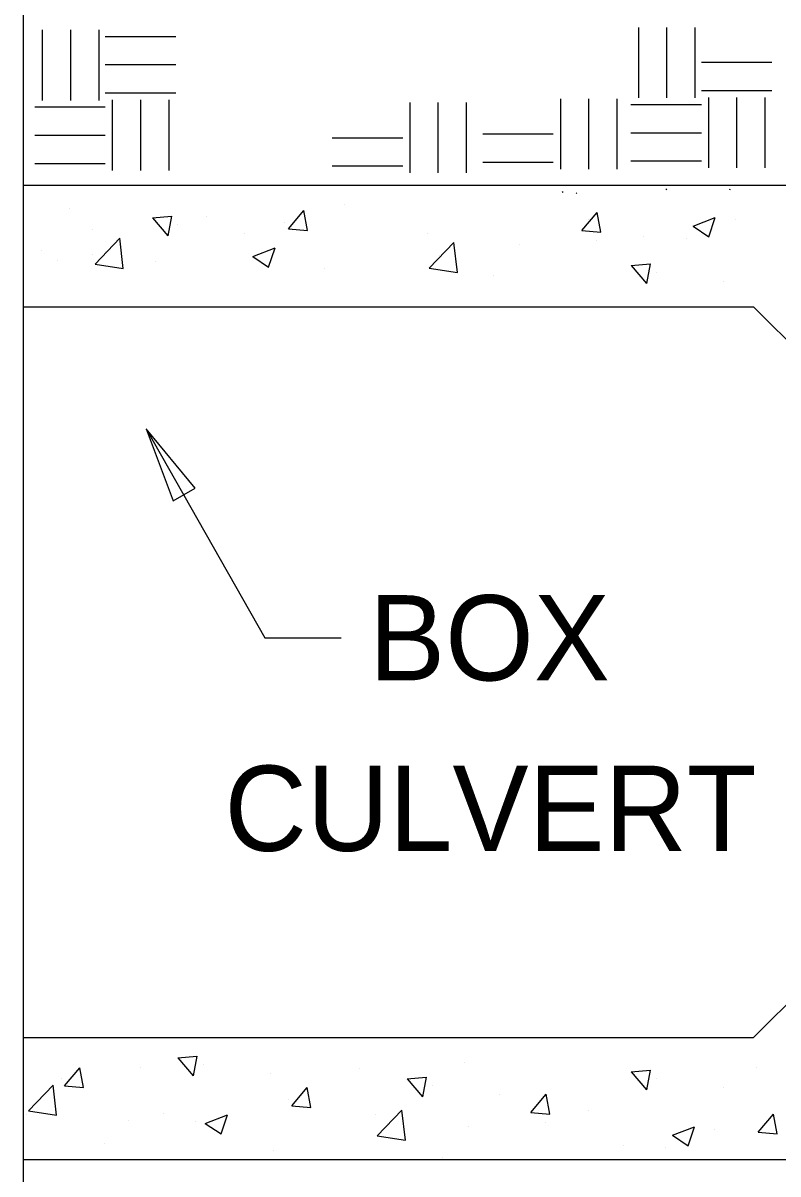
# Model space of a CAD drawing. Extents: x -1609 to 1184, y -412 to 394.
# Drawn here: x 598.388 to 600.868, y 242.766 to 246.546 of the extents above; entities that cross this region are included whole.
import ezdxf

# ---------------------------------------------------------------- set-up
doc = ezdxf.new("R2010")
doc.units = 0
for name, color, linetype in [('Default', 7, 'Continuous'), ('SH_Data', 7, 'Continuous'), ('ST_Text', 7, 'Continuous')]:
    doc.layers.add(name, color=color, linetype=linetype)

msp = doc.modelspace()

# ---------------------------------------------------------------- linework, layer by layer
at = {"layer": 'Default'}
for p, q in [((598.3883, 247.6355), (598.3883, 240.0476)), ((598.3883, 246.0133), (607.4734, 246.0133)), ((598.3883, 246.0133), (601.4383, 246.0133)), ((599.4451, 245.9484), (599.4451, 245.9484)), ((598.5411, 245.9371), (598.5411, 245.9371)), ((598.8141, 245.9061), (598.8764, 245.9116)), ((598.8141, 245.9061), (598.8643, 245.8463)), ((598.8764, 245.9116), (598.8643, 245.8463)), ((598.9918, 245.9118), (598.9918, 245.9118)), ((599.2603, 245.8701), (599.3105, 245.9299)), ((599.3225, 245.8646), (599.3105, 245.9299)), ((600.2242, 245.8638), (600.2744, 245.9236)), ((600.2449, 245.9018), (600.2449, 245.9018)), ((600.2864, 245.8583), (600.2744, 245.9236)), ((600.5895, 245.879), (600.6624, 245.907)), ((600.6413, 245.844), (600.6624, 245.9069)), ((598.6179, 245.8687), (598.6179, 245.8687)), ((598.8969, 245.8839), (598.8969, 245.8839)), ((599.2481, 245.8902), (599.2481, 245.8902)), ((599.2603, 245.8701), (599.3225, 245.8646)), ((600.2242, 245.8638), (600.2864, 245.8583)), ((600.5895, 245.879), (600.6413, 245.844)), ((600.7276, 245.8988), (600.7276, 245.8988)), ((598.6252, 245.7542), (598.7063, 245.8387)), ((598.7178, 245.7398), (598.7063, 245.8387)), ((599.1174, 245.853), (599.1174, 245.853)), ((599.7156, 245.8551), (599.7156, 245.8551)), ((599.7228, 245.7406), (599.8039, 245.8251)), ((599.8155, 245.7262), (599.8039, 245.8251)), ((600.2714, 245.8316), (600.2714, 245.8316)), ((600.4281, 245.8448), (600.4281, 245.8448)), ((600.5673, 245.8381), (600.5673, 245.8381)), ((598.4475, 245.799), (598.4475, 245.799)), ((598.66, 245.796), (598.66, 245.796)), ((599.1435, 245.7793), (599.2164, 245.8073)), ((599.1953, 245.7444), (599.2164, 245.8073)), ((600.0183, 245.8167), (600.0183, 245.8167)), ((598.5007, 245.7651), (598.5007, 245.7651)), ((598.6164, 245.7857), (598.6164, 245.7857)), ((598.6252, 245.7542), (598.7178, 245.7398)), ((598.8233, 245.7622), (598.8233, 245.7622)), ((599.1435, 245.7794), (599.1953, 245.7444)), ((599.7576, 245.7824), (599.7576, 245.7824)), ((600.3858, 245.7498), (600.4481, 245.7552)), ((600.3858, 245.7498), (600.436, 245.69)), ((600.4481, 245.7553), (600.436, 245.69)), ((599.3792, 245.7387), (599.3792, 245.7387)), ((599.7228, 245.7406), (599.8154, 245.7262)), ((599.9351, 245.7152), (599.9351, 245.7152)), ((600.4686, 245.7275), (600.4686, 245.7275)), ((600.6891, 245.6967), (600.6891, 245.6967)), ((598.3883, 245.6133), (600.7883, 245.6133)), ((600.7883, 245.6133), (601.1217, 245.28)), ((601.1217, 243.5467), (600.7883, 243.2133)), ((598.3883, 243.2133), (600.7883, 243.2133)), ((598.8969, 243.1472), (598.9591, 243.1526)), ((598.8969, 243.1472), (598.9471, 243.0874)), ((598.9591, 243.1527), (598.9471, 243.0874)), ((598.5248, 243.0547), (598.575, 243.1145)), ((598.5871, 243.0492), (598.5751, 243.1145)), ((598.774, 243.1148), (598.774, 243.1148)), ((598.9797, 243.1249), (598.9797, 243.1249)), ((599.4943, 243.1117), (599.4943, 243.1117)), ((599.8381, 243.1316), (599.8381, 243.1316)), ((600.3858, 243.1012), (600.4481, 243.1067)), ((600.4481, 243.1067), (600.436, 243.0414)), ((600.7979, 243.115), (600.7979, 243.115)), ((598.5133, 243.0805), (598.5133, 243.0805)), ((599.2001, 243.0941), (599.2001, 243.0941)), ((599.6505, 243.0782), (599.7128, 243.0837)), ((599.6505, 243.0782), (599.7007, 243.0184)), ((599.7128, 243.0837), (599.7007, 243.0184)), ((600.3858, 243.1012), (600.436, 243.0414)), ((600.4686, 243.0789), (600.4686, 243.0789)), ((598.4059, 242.9731), (598.487, 243.0577)), ((598.4986, 242.9587), (598.487, 243.0576)), ((598.5248, 243.0547), (598.5871, 243.0492)), ((599.2718, 242.9893), (599.322, 243.0492)), ((599.334, 242.9838), (599.322, 243.0491)), ((599.7333, 243.0559), (599.7333, 243.0559)), ((600.0564, 242.968), (600.1066, 243.0278)), ((600.1186, 242.9625), (600.1066, 243.0278)), ((600.6891, 243.0481), (600.6891, 243.0481)), ((599.2595, 243.0095), (599.2595, 243.0095)), ((599.9538, 243.0251), (599.9538, 243.0251)), ((598.3982, 242.9622), (598.3982, 242.9622)), ((598.4059, 242.9731), (598.4986, 242.9588)), ((598.8493, 242.9634), (598.8493, 242.9634)), ((598.9872, 242.9318), (599.0601, 242.9598)), ((599.039, 242.8969), (599.0601, 242.9598)), ((599.2718, 242.9893), (599.334, 242.9839)), ((599.5478, 242.9593), (599.5478, 242.9593)), ((599.5517, 242.8907), (599.6328, 242.9752)), ((599.6444, 242.8763), (599.6328, 242.9752)), ((600.0564, 242.968), (600.1186, 242.9625)), ((600.2449, 242.9728), (600.2449, 242.9728)), ((600.8033, 242.9027), (600.8535, 242.9625)), ((600.8655, 242.8972), (600.8535, 242.9625)), ((598.7336, 242.9428), (598.7336, 242.9428)), ((598.9541, 242.9388), (598.9541, 242.9388)), ((598.9872, 242.9318), (599.039, 242.8969)), ((599.5865, 242.9325), (599.5865, 242.9325)), ((599.8505, 242.9209), (599.8505, 242.9209)), ((600.1036, 242.9358), (600.1036, 242.9358)), ((600.5214, 242.8925), (600.5943, 242.9204)), ((600.5732, 242.8575), (600.5943, 242.9204)), ((599.5517, 242.8907), (599.6443, 242.8763)), ((600.5214, 242.8925), (600.5732, 242.8575)), ((600.6595, 242.9123), (600.6595, 242.9123)), ((600.8033, 242.9027), (600.8655, 242.8972)), ((598.6555, 242.8664), (598.6555, 242.8664)), ((599.2114, 242.8429), (599.2114, 242.8429)), ((600.3601, 242.8582), (600.3601, 242.8582)), ((600.4993, 242.8515), (600.4993, 242.8515)), ((598.3883, 242.8133), (601.4383, 242.8133)), ((599.7673, 242.8194), (599.7673, 242.8194))]:
    msp.add_line(p, q, dxfattribs=at)
msp.add_lwpolyline([(598.8815, 244.9761), (598.9536, 245.0179), (598.7924, 245.2133)], close=True, dxfattribs=at)
at = {"layer": 'ST_Text'}
for p, q in [((598.4518, 246.5232), (598.4518, 246.2915)), ((598.5444, 246.5232), (598.5444, 246.2915)), ((598.6371, 246.5232), (598.6371, 246.2915)), ((600.4101, 246.5313), (600.4101, 246.2997)), ((600.5027, 246.5313), (600.5027, 246.2997)), ((600.5954, 246.5313), (600.5954, 246.2997)), ((598.6585, 246.5016), (598.8902, 246.5016)), ((598.6585, 246.409), (598.8902, 246.409)), ((600.6168, 246.4172), (600.8485, 246.4172)), ((598.6585, 246.3163), (598.8902, 246.3163)), ((600.6168, 246.3245), (600.8485, 246.3245)), ((598.6817, 246.2931), (598.6817, 246.0615)), ((598.7744, 246.2931), (598.7744, 246.0615)), ((598.867, 246.2931), (598.867, 246.0615)), ((599.6588, 246.285), (599.6588, 246.0533)), ((599.7515, 246.285), (599.7515, 246.0533)), ((599.8441, 246.285), (599.8441, 246.0533)), ((600.1535, 246.2972), (600.1535, 246.0656)), ((600.2461, 246.2972), (600.2461, 246.0656)), ((600.3388, 246.2972), (600.3388, 246.0656)), ((600.64, 246.3013), (600.64, 246.0697)), ((600.7326, 246.3013), (600.7326, 246.0697)), ((600.8253, 246.3013), (600.8253, 246.0697)), ((598.4269, 246.27), (598.6585, 246.27)), ((600.3852, 246.2782), (600.6168, 246.2782)), ((598.4269, 246.1773), (598.6585, 246.1773)), ((599.404, 246.1691), (599.6356, 246.1691)), ((599.8987, 246.1814), (600.1303, 246.1814)), ((600.3852, 246.1855), (600.6168, 246.1855)), ((600.3852, 246.0929), (600.6168, 246.0929)), ((598.4269, 246.0847), (598.6585, 246.0847)), ((599.404, 246.0765), (599.6356, 246.0765)), ((599.8987, 246.0888), (600.1303, 246.0888)), ((600.1596, 245.9919), (600.1611, 245.9895)), ((600.2059, 245.9876), (600.2075, 245.9853)), ((600.5012, 245.9975), (600.5028, 246.0011)), ((600.7099, 245.9975), (600.7115, 246.0011)), ((598.7924, 245.2133), (599.1832, 244.5265)), ((599.1832, 244.5265), (599.433, 244.5265))]:
    msp.add_line(p, q, dxfattribs=at)

# ---------------------------------------------------------------- texts
at = {"layer": 'SH_Data'}
for s, p in [('BOX', (599.5253, 244.3866)), ('CULVERT', (599.0502, 243.8266))]:
    msp.add_text(s, height=0.28, dxfattribs=at).set_placement(p)

doc.saveas('drawing.dxf')
